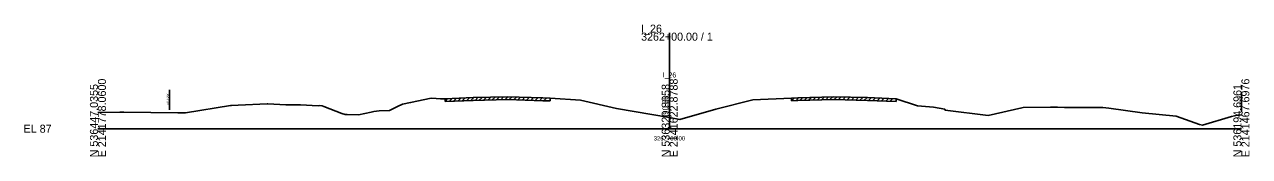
# Model space of a CAD drawing. Extents: x -13101 to 4803, y -924 to 22390.
# Drawn here: x 2974.3 to 3402.8, y 10990.3 to 11036.4 of the extents above; entities that cross this region are included whole.
import ezdxf

# ---------------------------------------------------------------- set-up
doc = ezdxf.new("R2010")
doc.units = 0
for name, color, linetype in [('RD_GPK_XS_Cell', 7, 'Continuous'), ('RD_XS_ExGround', 7, 'Continuous'), ('RD_XS_ExPaveRet', 7, 'Continuous'), ('RD_XS_ExRW', 7, 'Continuous'), ('RD_XS_TX_Baseline', 7, 'Continuous'), ('RD_XS_TX_Elev_EX', 7, 'Continuous'), ('RD_XS_TX_Station', 7, 'Continuous')]:
    doc.layers.add(name, color=color, linetype=linetype)

msp = doc.modelspace()

# ---------------------------------------------------------------- linework, layer by layer
at = {"layer": 'RD_GPK_XS_Cell'}
for p, q in [((3200, 11000), (3200, 11033.53)), ((3000, 11000), (3200, 11000)), ((3200, 11000), (3400, 11000))]:
    msp.add_line(p, q, dxfattribs=at)
at = {"layer": 'RD_XS_ExGround'}
msp.add_lwpolyline([(3000, 11005.6), (3007.7, 11005.76), (3009.08, 11005.79), (3027.99, 11005.53), (3030.06, 11005.51), (3030.68, 11005.52), (3046.35, 11008.11), (3046.75, 11008.12), (3049.04, 11008.2), (3059.14, 11008.66), (3059.45, 11008.68), (3065.77, 11008.32), (3067.36, 11008.34), (3068.59, 11008.36), (3069.05, 11008.37), (3070.88, 11008.33), (3077.03, 11007.99), (3077.5, 11008.06), (3078.45, 11007.97), (3079.05, 11007.7), (3085.29, 11005.29), (3086.54, 11004.94), (3087.14, 11004.94), (3091.1, 11004.89), (3095.56, 11005.8), (3096.55, 11006.04), (3098.4, 11006.2), (3101.96, 11006.32), (3104.77, 11007.76), (3106.56, 11008.54), (3109.37, 11009.11), (3116.57, 11010.64), (3118.29, 11010.57), (3119.85, 11010.47), (3121.41, 11010.47), (3131.31, 11010.86), (3143.26, 11011.17), (3155.67, 11010.74), (3158.24, 11010.68), (3168.77, 11009.96), (3181.37, 11007.1), (3200, 11003.88), (3203.52, 11003.26), (3216.18, 11006.85), (3229.15, 11010.06), (3242.58, 11010.71), (3244.83, 11010.81), (3257.45, 11011.18), (3269.24, 11010.88), (3279.2, 11010.47), (3286.73, 11008.01), (3292.26, 11007.57), (3296.21, 11006.81), (3296.35, 11006.48), (3311.4, 11004.6), (3323.2, 11007.33), (3323.65, 11007.38), (3333.28, 11007.56), (3335.71, 11007.49), (3338.15, 11007.36), (3350.99, 11007.35), (3351.5, 11007.35), (3353.67, 11007.15), (3365.31, 11005.54), (3377.22, 11004.32), (3385.35, 11001.52), (3386.41, 11001.27), (3396.5, 11004.31), (3398.6, 11004.72), (3400, 11004.84)], dxfattribs=at)
at = {"layer": 'RD_XS_ExPaveRet'}
for p, q in [((3121.41, 11009.47), (3122.45, 11010.51)), ((3121.41, 11009.47), (3121.41, 11010.47)), ((3121.41, 11009.47), (3131.31, 11009.86)), ((3122.91, 11009.52), (3123.95, 11010.57)), ((3124.41, 11009.58), (3125.45, 11010.62)), ((3125.91, 11009.64), (3126.95, 11010.68)), ((3127.41, 11009.7), (3128.45, 11010.74)), ((3128.91, 11009.76), (3129.95, 11010.8)), ((3130.41, 11009.82), (3131.45, 11010.86)), ((3131.31, 11009.86), (3143.26, 11010.17)), ((3131.91, 11009.87), (3132.93, 11010.9)), ((3133.41, 11009.91), (3134.43, 11010.94)), ((3134.91, 11009.95), (3135.93, 11010.98)), ((3136.41, 11009.99), (3137.43, 11011.02)), ((3137.91, 11010.03), (3138.93, 11011.06)), ((3139.41, 11010.07), (3140.43, 11011.1)), ((3140.91, 11010.11), (3141.93, 11011.14)), ((3142.41, 11010.15), (3143.42, 11011.16)), ((3143.26, 11010.17), (3155.67, 11009.74)), ((3143.91, 11010.15), (3144.87, 11011.11)), ((3145.41, 11010.1), (3146.37, 11011.06)), ((3146.91, 11010.04), (3147.87, 11011.01)), ((3148.41, 11009.99), (3149.37, 11010.96)), ((3149.91, 11009.94), (3150.87, 11010.91)), ((3151.41, 11009.89), (3152.37, 11010.85)), ((3152.91, 11009.83), (3153.87, 11010.8)), ((3154.41, 11009.78), (3155.37, 11010.75)), ((3155.67, 11009.74), (3158.24, 11009.68)), ((3155.91, 11009.73), (3156.89, 11010.71)), ((3158.24, 11010.68), (3158.24, 11009.68)), ((3242.58, 11009.71), (3243.62, 11010.76)), ((3242.58, 11009.71), (3242.58, 11010.71)), ((3242.58, 11009.71), (3244.83, 11009.81)), ((3244.08, 11009.78), (3245.12, 11010.82)), ((3244.83, 11009.81), (3257.45, 11010.18)), ((3245.58, 11009.83), (3246.61, 11010.86)), ((3247.08, 11009.87), (3248.11, 11010.9)), ((3248.58, 11009.92), (3249.61, 11010.95)), ((3250.08, 11009.96), (3251.11, 11010.99)), ((3251.58, 11010.01), (3252.61, 11011.04)), ((3253.08, 11010.05), (3254.11, 11011.08)), ((3254.58, 11010.09), (3255.61, 11011.12)), ((3256.08, 11010.14), (3257.11, 11011.17)), ((3257.45, 11010.18), (3269.24, 11009.88)), ((3257.58, 11010.17), (3258.55, 11011.15)), ((3259.08, 11010.14), (3260.05, 11011.11)), ((3260.58, 11010.1), (3261.55, 11011.07)), ((3262.08, 11010.06), (3263.05, 11011.04)), ((3263.58, 11010.02), (3264.55, 11011)), ((3265.08, 11009.99), (3266.05, 11010.96)), ((3266.58, 11009.95), (3267.55, 11010.92)), ((3268.08, 11009.91), (3269.05, 11010.89)), ((3269.24, 11009.88), (3279.2, 11009.47)), ((3269.58, 11009.87), (3270.54, 11010.83)), ((3271.08, 11009.81), (3272.04, 11010.77)), ((3272.58, 11009.74), (3273.54, 11010.7)), ((3274.08, 11009.68), (3275.04, 11010.64)), ((3275.58, 11009.62), (3276.54, 11010.58)), ((3277.08, 11009.56), (3278.04, 11010.52)), ((3279.2, 11010.47), (3279.2, 11009.47))]:
    msp.add_line(p, q, dxfattribs=at)
at = {"layer": 'RD_XS_ExRW'}
for p, q in [((3025, 11006.57), (3025, 11013.57)), ((3400, 11005.84), (3400, 11012.84))]:
    msp.add_line(p, q, dxfattribs=at)

# ---------------------------------------------------------------- texts
at = {"layer": 'RD_GPK_XS_Cell'}
for s, p in [('I_26', (3190, 11033.53)), ('3262+00.00 / 1', (3190, 11030.73)), ('EL 87', (2974, 10998.6))]:
    msp.add_text(s, height=2.8, dxfattribs=at).set_placement(p)
for s, p in [('N 536447.0355', (3000, 10990)), ('E 2141778.0600', (3002.8, 10990)), ('N 536320.8658', (3200, 10990)), ('E 2141622.8788', (3202.8, 10990)), ('N 536194.6961', (3400, 10990)), ('E 2141467.6976', (3402.8, 10990))]:
    msp.add_text(s, height=2.8, rotation=90, dxfattribs=at).set_placement(p)
at = {"layer": 'RD_XS_ExRW'}
for p in [(3024.75, 11008.25), (3399.75, 11007.53)]:
    msp.add_text('EX. R/W ', height=0.75, rotation=90, dxfattribs=at).set_placement(p)
at = {"layer": 'RD_XS_TX_Baseline'}
msp.add_text('I_26', height=1.75, dxfattribs=at).set_placement((3197.6, 11017.88))
at = {"layer": 'RD_XS_TX_Elev_EX'}
msp.add_text('90.88', height=2, rotation=90, dxfattribs=at).set_placement((3199.5, 11004.88))
at = {"layer": 'RD_XS_TX_Station'}
msp.add_text('3262+00.00', height=1.5, dxfattribs=at).set_placement((3194.41, 10995.88))

doc.saveas('drawing.dxf')
